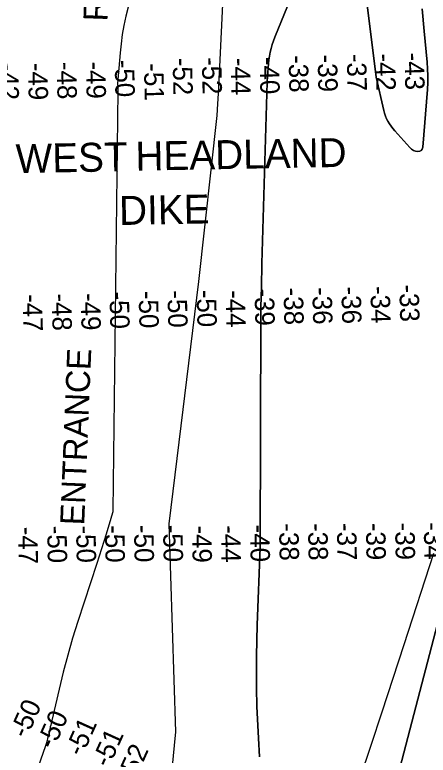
# Model space of a CAD drawing. Extents: x 3925854 to 3964121, y 224593 to 250589.
# Drawn here: x 3943605 to 3945031, y 238574 to 241130 of the extents above; entities that cross this region are included whole.
import ezdxf

# ---------------------------------------------------------------- set-up
doc = ezdxf.new("R2010")
doc.units = 0
for name, color, linetype in [('V-LEVE-IDEN', 7, 'Continuous'), ('V-RIVR-RANG', 7, 'Continuous'), ('V-RIVR-RANG-IDEN', 7, 'Continuous'), ('V-TOPO-DPTH', 7, 'Continuous'), ('V-TOPO-MAJR', 7, 'Continuous'), ('V-TOPO-MINR', 7, 'Continuous')]:
    doc.layers.add(name, color=color, linetype=linetype)

msp = doc.modelspace()

# ---------------------------------------------------------------- linework, layer by layer
at = {"layer": 'V-TOPO-DPTH'}
for points in [[(3945010.246, 241151.029), (3945017.429, 241073.981), (3945027.476, 240966.921), (3945029.08, 240943.402), (3945029.886, 240919.877), (3945029.496, 240896.341), (3945028.307, 240872.797), (3945013.1, 240672.836), (3945010.871, 240666.524), (3945007.393, 240661.694), (3945002.042, 240659.088), (3944995.442, 240657.965), (3944987.68, 240659.62), (3944980.443, 240662.311), (3944973.994, 240666.555), (3944968.07, 240671.836), (3944916.325, 240729.926), (3944909.799, 240737.71), (3944903.599, 240745.732), (3944897.891, 240754.109), (3944892.509, 240762.725), (3944887.818, 240771.694), (3944883.707, 240780.89), (3944880.466, 240790.428), (3944877.804, 240800.193), (3944852.081, 240915.473), (3944852.073, 240915.563), (3944810.754, 241248.384)], [(3945010.246, 241151.029), (3945017.429, 241073.981), (3945027.476, 240966.921), (3945029.08, 240943.402), (3945029.886, 240919.877), (3945029.496, 240896.341), (3945028.307, 240872.797), (3945013.1, 240672.836), (3945010.871, 240666.524), (3945007.393, 240661.694), (3945002.042, 240659.088), (3944995.442, 240657.965), (3944987.68, 240659.62), (3944980.443, 240662.311), (3944973.994, 240666.555), (3944968.07, 240671.836), (3944916.325, 240729.926), (3944909.799, 240737.71), (3944903.599, 240745.732), (3944897.891, 240754.109), (3944892.509, 240762.725), (3944887.818, 240771.694), (3944883.707, 240780.89), (3944880.466, 240790.428), (3944877.804, 240800.193), (3944852.081, 240915.473), (3944852.073, 240915.563), (3944810.754, 241248.384)], [(3944556.211, 241186.228), (3944502.527, 241053.426), (3944497.721, 241040.637), (3944493.343, 241027.715), (3944489.607, 241014.592), (3944486.3, 241001.336), (3944483.64, 240987.934), (3944481.409, 240974.471), (3944479.824, 240960.917), (3944478.669, 240947.302), (3944476.695, 240914.854), (3944476.453, 240910.535), (3944476.239, 240906.215), (3944476.065, 240901.892), (3944475.919, 240897.569), (3944457.755, 240272.202), (3944456.987, 240244.161), (3944456.282, 240216.118), (3944455.671, 240188.073), (3944455.122, 240160.027), (3944454.36, 240117.505), (3944454.253, 240110.718), (3944454.166, 240103.931), (3944454.109, 240097.144), (3944454.072, 240090.356), (3944451.39, 239291.34), (3944441.379, 239024.471), (3944439.796, 238970.116), (3944438.821, 238915.757), (3944438.759, 238861.388), (3944439.304, 238807.014), (3944440.505, 238741.751), (3944441.086, 238720.012), (3944441.906, 238698.284), (3944443.085, 238676.572), (3944444.505, 238654.872), (3944445.962, 238633.172), (3944447.23, 238611.463), (3944448.214, 238589.739), (3944449.008, 238568.005)], [(3944556.211, 241186.228), (3944502.527, 241053.426), (3944497.721, 241040.637), (3944493.343, 241027.715), (3944489.607, 241014.592), (3944486.3, 241001.336), (3944483.64, 240987.934), (3944481.409, 240974.471), (3944479.824, 240960.917), (3944478.669, 240947.302), (3944476.695, 240914.854), (3944476.453, 240910.535), (3944476.239, 240906.215), (3944476.065, 240901.892), (3944475.919, 240897.569), (3944457.755, 240272.202), (3944456.987, 240244.161), (3944456.282, 240216.118), (3944455.671, 240188.073), (3944455.122, 240160.027), (3944454.36, 240117.505), (3944454.253, 240110.718), (3944454.166, 240103.931), (3944454.109, 240097.144), (3944454.072, 240090.356), (3944451.39, 239291.34), (3944441.379, 239024.471), (3944439.796, 238970.116), (3944438.821, 238915.757), (3944438.759, 238861.388), (3944439.304, 238807.014), (3944440.505, 238741.751), (3944441.086, 238720.012), (3944441.906, 238698.284), (3944443.085, 238676.572), (3944444.505, 238654.872), (3944445.962, 238633.172), (3944447.23, 238611.463), (3944448.214, 238589.739), (3944449.008, 238568.005)], [(3944795.666, 238492.834), (3944834.327, 238608.414), (3944872.687, 238724.094), (3944910.595, 238839.923), (3944948.202, 238955.851), (3945050.084, 239272.016)], [(3944795.666, 238492.834), (3944834.327, 238608.414), (3944872.687, 238724.094), (3944910.595, 238839.923), (3944948.202, 238955.851), (3945050.084, 239272.016)], [(3945105.18, 239185.923), (3944933.068, 238528.846), (3944919.053, 238475.395), (3944905.02, 238421.948), (3944890.96, 238368.509), (3944876.882, 238315.074), (3944849.833, 238212.51), (3944849.301, 238210.354), (3944848.4, 238206.007), (3944848.03, 238203.817), (3944847.578, 238200.848), (3944847.679, 238200.423)]]:
    msp.add_lwpolyline(points, dxfattribs=at)
at = {"layer": 'V-TOPO-MAJR'}
for points in [[(3944137.613, 239373.047), (3944240.058, 240209.465), (3944303.874, 240782.767), (3944306.071, 240822.55), (3944308.924, 240877.648), (3944309.548, 240889.892), (3944310.161, 240902.136), (3944310.756, 240914.381), (3944311.338, 240926.626), (3944338.447, 241505.534), (3944339.786, 241536.44), (3944340.98, 241567.352), (3944341.956, 241598.272), (3944342.788, 241629.196), (3944343.976, 241680.033), (3944344.087, 241685.543), (3944344.172, 241691.054), (3944344.221, 241696.565), (3944344.245, 241702.076), (3944344.816, 242297.233), (3944344.906, 242330.582), (3944345.072, 242363.931)], [(3943995.809, 241156.661), (3943988.539, 241125.358), (3943981.906, 241093.957), (3943976.179, 241062.411), (3943971.81, 241030.649), (3943968.347, 240998.743), (3943961.442, 240919.272), (3943960.586, 240906.377), (3943960.082, 240893.476), (3943960.104, 240880.566), (3943960.478, 240867.648), (3943943.823, 239417.454)], [(3943943.823, 239417.454), (3943943.074, 239414.482), (3943938.99, 239399.052), (3943934.628, 239383.699), (3943930.082, 239368.396), (3943920.649, 239337.657), (3943912.762, 239312.204), (3943904.78, 239286.78), (3943896.658, 239261.401), (3943888.443, 239236.052), (3943822.998, 239036.007), (3943804.854, 238977.925), (3943787.756, 238919.552), (3943772.227, 238860.742), (3943757.743, 238801.641), (3943732.979, 238694.393), (3943731.672, 238688.695), (3943730.376, 238682.994), (3943729.097, 238677.29), (3943727.83, 238671.583), (3943725.642, 238661.663), (3943723.963, 238654.204), (3943722.241, 238646.755), (3943720.455, 238639.321), (3943718.626, 238631.898), (3943716.664, 238624.512), (3943714.565, 238617.168), (3943712.264, 238609.884), (3943709.827, 238602.641), (3943599.081, 238288.01)], [(3944146.631, 238511.638), (3944156.344, 238606.979), (3944161.157, 238654.64), (3944137.613, 239373.047)]]:
    msp.add_lwpolyline(points, dxfattribs=at)
at = {"layer": 'V-TOPO-MINR'}
for points in [[(3944810.754, 241248.384), (3944852.073, 240915.563), (3944852.081, 240915.473), (3944877.804, 240800.193), (3944880.466, 240790.428), (3944883.707, 240780.89), (3944887.818, 240771.694), (3944892.509, 240762.725), (3944897.891, 240754.109), (3944903.599, 240745.732), (3944909.799, 240737.71), (3944916.325, 240729.926), (3944968.07, 240671.836), (3944973.994, 240666.555), (3944980.443, 240662.311), (3944987.68, 240659.62), (3944995.442, 240657.965), (3945002.042, 240659.088), (3945007.393, 240661.694), (3945010.871, 240666.524), (3945013.1, 240672.836), (3945028.307, 240872.797), (3945029.496, 240896.341), (3945029.886, 240919.877), (3945029.08, 240943.402), (3945027.476, 240966.921), (3945017.429, 241073.981), (3945010.246, 241151.029)], [(3944449.008, 238568.005), (3944448.214, 238589.739), (3944447.23, 238611.463), (3944445.962, 238633.172), (3944444.505, 238654.872), (3944443.085, 238676.572), (3944441.906, 238698.284), (3944441.086, 238720.012), (3944440.505, 238741.751), (3944439.304, 238807.014), (3944438.759, 238861.388), (3944438.821, 238915.757), (3944439.796, 238970.116), (3944441.379, 239024.471), (3944451.39, 239291.34), (3944454.072, 240090.356), (3944454.109, 240097.144), (3944454.166, 240103.931), (3944454.253, 240110.718), (3944454.36, 240117.505), (3944455.122, 240160.027), (3944455.671, 240188.073), (3944456.282, 240216.118), (3944456.987, 240244.161), (3944457.755, 240272.202), (3944475.919, 240897.569), (3944476.065, 240901.892), (3944476.239, 240906.215), (3944476.453, 240910.535), (3944476.695, 240914.854), (3944478.669, 240947.302), (3944479.824, 240960.917), (3944481.409, 240974.471), (3944483.64, 240987.934), (3944486.3, 241001.336), (3944489.607, 241014.592), (3944493.343, 241027.715), (3944497.721, 241040.637), (3944502.527, 241053.426), (3944556.211, 241186.228)], [(3944795.666, 238492.834), (3944834.327, 238608.414), (3944872.687, 238724.094), (3944910.595, 238839.923), (3944948.202, 238955.851), (3945050.084, 239272.016)], [(3944847.679, 238200.423), (3944847.578, 238200.848), (3944848.03, 238203.817), (3944848.4, 238206.007), (3944849.301, 238210.354), (3944849.833, 238212.51), (3944876.882, 238315.074), (3944890.96, 238368.509), (3944905.02, 238421.948), (3944919.053, 238475.395), (3944933.068, 238528.846), (3945105.18, 239185.923)]]:
    msp.add_lwpolyline(points, dxfattribs=at)

# ---------------------------------------------------------------- texts
at = {"layer": 'V-LEVE-IDEN'}
for s, p in [('WEST', (3943609.136, 240583.567)), ('HEADLAND', (3944022.289, 240591.958)), ('DIKE', (3943965.799, 240404.476))]:
    msp.add_text(s, height=99.9998, rotation=1.067956, dxfattribs=at).set_placement(p)
at = {"layer": 'V-RIVR-RANG'}
for s, rotation, p in [('-39', 271.263028, (3944649.763, 240992.374)), ('-37', 271.263028, (3944750.321, 240995.388)), ('-42', 271.263028, (3944850.02, 240996.511)), ('-43', 271.263028, (3944949.378, 240999.484)), ('-48', 271.263028, (3943749.9, 240967.324)), ('-49', 271.263028, (3943850.387, 240969.005)), ('-50', 271.263028, (3943949.787, 240974.618)), ('-52', 271.263028, (3944149.685, 240981.385)), ('-52', 271.263028, (3944250.355, 240983.863)), ('-44', 271.263028, (3944349.835, 240981.298)), ('-40', 271.263028, (3944449.582, 240984.808)), ('-38', 271.263028, (3944549.676, 240990.702)), ('-42', 271.263028, (3943550.213, 240964.52)), ('-49', 271.263028, (3943650.647, 240964.089)), ('-51', 271.263028, (3944050.782, 240962.328)), ('-50', 271.447, (3943931.654, 240174.322)), ('-50', 271.447, (3944032.232, 240176.384)), ('-50', 271.447, (3944131.612, 240178.422)), ('-50', 271.447, (3944232.29, 240180.486)), ('-44', 271.447, (3944332.249, 240179.37)), ('-39', 271.447, (3944432.135, 240185.112)), ('-38', 271.447, (3944532.094, 240187.953)), ('-36', 271.447, (3944631.387, 240189.461)), ('-36', 271.447, (3944731.566, 240191.515)), ('-34', 271.447, (3944831.651, 240193.303)), ('-33', 271.447, (3944931.544, 240198.781)), ('-47', 271.447, (3943632.083, 240165.553)), ('-48', 271.447, (3943732.455, 240167.863)), ('-49', 271.447, (3943832.354, 240169.12)), ('-47', 271.030833, (3943616.314, 239362.552)), ('-50', 271.030833, (3943716.863, 239366.032)), ('-50', 271.030833, (3943816.76, 239366.88)), ('-50', 271.030833, (3943916.056, 239367.724)), ('-50', 271.030833, (3944016.452, 239368.576)), ('-50', 271.030833, (3944116.649, 239369.427)), ('-49', 271.030833, (3944216.302, 239367.108)), ('-44', 271.030833, (3944315.999, 239367.955)), ('-40', 271.030833, (3944416.476, 239369.863)), ('-38', 271.030833, (3944516.811, 239374.144)), ('-38', 271.030833, (3944616.607, 239374.992)), ('-37', 271.030833, (3944716.108, 239375.585)), ('-39', 271.030833, (3944816.214, 239375.895)), ('-39', 271.030833, (3944917.01, 239376.751)), ('-34', 271.030833, (3945015.907, 239377.591)), ('-50', 65.717472, (3943645.722, 238628.814)), ('-50', 65.717472, (3943738.289, 238590.715)), ('-51', 65.717472, (3943837.115, 238566.006)), ('-51', 65.717472, (3943929.404, 238528.022)), ('-52', 65.717472, (3944015.229, 238474.738))]:
    msp.add_text(s, height=67, rotation=rotation, dxfattribs=at).set_placement(p)
at = {"layer": 'V-RIVR-RANG-IDEN'}
for s, rotation, p in [('RANGE', 87.901742, (3943924.582, 241106.79)), ('ENTRANCE', 87.67414, (3943844.54, 239366.781))]:
    msp.add_text(s, height=83, rotation=rotation, dxfattribs=at).set_placement(p)

doc.saveas('drawing.dxf')
